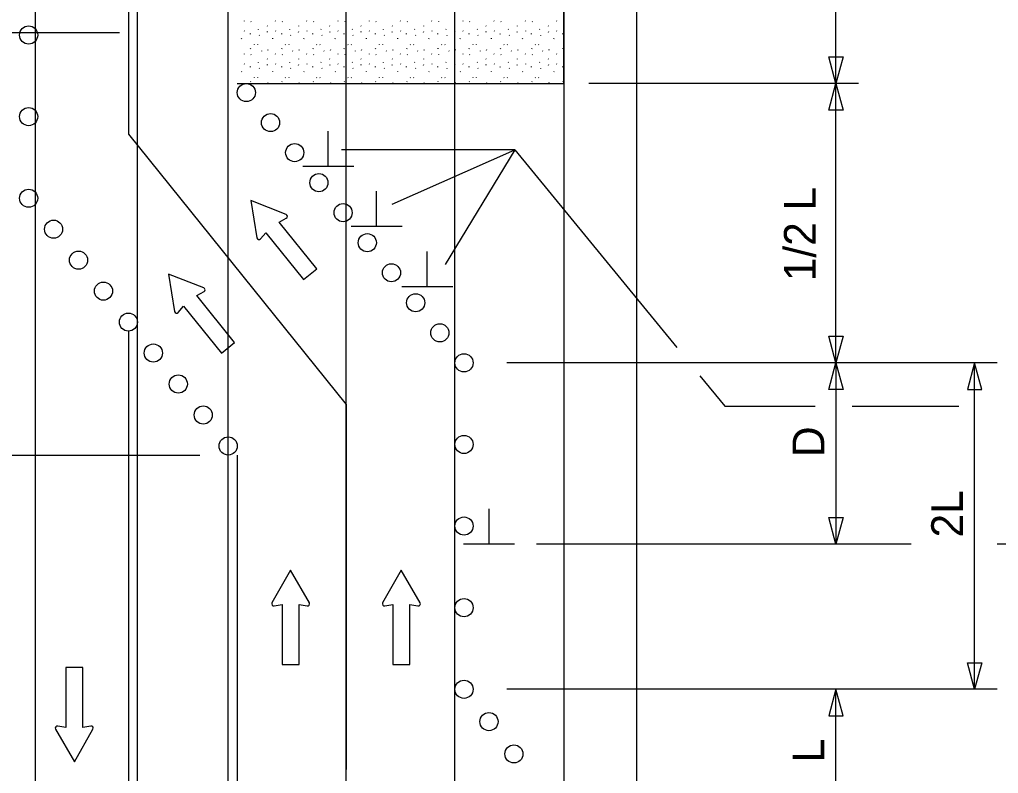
# Model space of a CAD drawing. Extents: x 16723 to 18475, y 7015 to 8267.
# Drawn here: x 17031.7 to 17247.5, y 7602.8 to 7769.1 of the extents above; entities that cross this region are included whole.
import ezdxf

# ---------------------------------------------------------------- set-up
doc = ezdxf.new("R2010")
doc.units = 0
for name, color, linetype in [('ALI_LEGAL_EX', 7, 'Continuous'), ('MT_SCRATCH_LEVEL_A', 7, 'Continuous'), ('MT_SCRATCH_LEVEL_E', 7, 'Continuous'), ('PAVT_EDGE_EX', 7, 'Continuous'), ('TRAFFIC_SIGNS_PR', 7, 'Continuous'), ('TYPICAL_TEXT_DIMEN_PR', 7, 'Continuous')]:
    doc.layers.add(name, color=color, linetype=linetype)

msp = doc.modelspace()

# ---------------------------------------------------------------- linework, layer by layer
at = {"layer": 'ALI_LEGAL_EX'}
for p, q in [((17057.71, 7347.02), (17057.71, 8219.23)), ((17077.71, 7347.02), (17077.71, 8219.23)), ((17103.71, 7341.97), (17103.71, 8214.17)), ((17127.71, 7341.97), (17127.71, 8214.17))]:
    msp.add_line(p, q, dxfattribs=at)
for points in [[(17077.71, 7754.97), (17077.71, 7766.97)], [(17103.71, 7741.97), (17103.71, 7766.97)], [(17127.71, 7741.97), (17127.71, 7766.97)], [(17057.71, 7641.97), (17057.71, 7666.97)], [(17077.71, 7641.97), (17077.71, 7666.97)], [(17103.71, 7641.97), (17103.71, 7666.97)], [(17127.71, 7641.97), (17127.71, 7666.97)]]:
    msp.add_lwpolyline(points, dxfattribs=at)
at = {"layer": 'MT_SCRATCH_LEVEL_A'}
for p, q in [((17151.71, 7867.21), (17151.71, 7754.97)), ((17151.71, 7754.97), (17151.71, 7783.03)), ((17081.21, 7768.78), (17081.26, 7768.7)), ((17082.74, 7768.64), (17082.79, 7768.56)), ((17088.1, 7768.78), (17088.15, 7768.7)), ((17089.63, 7768.64), (17089.68, 7768.56)), ((17094.98, 7768.78), (17095.04, 7768.7)), ((17096.51, 7768.64), (17096.57, 7768.56)), ((17101.87, 7768.78), (17101.92, 7768.7)), ((17103.4, 7768.64), (17103.45, 7768.56)), ((17108.76, 7768.78), (17108.81, 7768.7)), ((17110.29, 7768.64), (17110.34, 7768.56)), ((17115.65, 7768.78), (17115.7, 7768.7)), ((17117.18, 7768.64), (17117.23, 7768.56)), ((17122.53, 7768.78), (17122.59, 7768.7)), ((17124.06, 7768.64), (17124.12, 7768.56)), ((17129.42, 7768.78), (17129.47, 7768.7)), ((17130.95, 7768.64), (17131, 7768.56)), ((17136.31, 7768.78), (17136.36, 7768.7)), ((17137.84, 7768.64), (17137.89, 7768.56)), ((17143.2, 7768.78), (17143.25, 7768.7)), ((17144.73, 7768.64), (17144.78, 7768.56)), ((17150.08, 7768.78), (17150.14, 7768.7)), ((17151.61, 7768.64), (17151.67, 7768.56)), ((17081.26, 7766.57), (17081.31, 7766.49)), ((17082.54, 7766), (17082.55, 7765.88)), ((17084.38, 7766.85), (17084.43, 7766.97)), ((17084.57, 7765.65), (17084.62, 7765.58)), ((17086.31, 7767.72), (17086.36, 7767.65)), ((17086.35, 7766.32), (17086.4, 7766.44)), ((17088.15, 7766.57), (17088.2, 7766.49)), ((17089.43, 7766), (17089.44, 7765.88)), ((17091.27, 7766.85), (17091.32, 7766.97)), ((17091.46, 7765.65), (17091.51, 7765.58)), ((17093.19, 7767.72), (17093.24, 7767.65)), ((17093.24, 7766.32), (17093.29, 7766.44)), ((17095.03, 7766.57), (17095.08, 7766.49)), ((17096.31, 7766), (17096.33, 7765.88)), ((17098.16, 7766.85), (17098.21, 7766.97)), ((17098.34, 7765.65), (17098.4, 7765.58)), ((17100.08, 7767.72), (17100.13, 7767.65)), ((17100.12, 7766.32), (17100.17, 7766.44)), ((17101.92, 7766.57), (17101.97, 7766.49)), ((17103.2, 7766), (17103.22, 7765.88)), ((17105.04, 7766.85), (17105.1, 7766.97)), ((17105.23, 7765.65), (17105.28, 7765.58)), ((17106.97, 7767.72), (17107.02, 7767.65)), ((17107.01, 7766.32), (17107.06, 7766.44)), ((17108.81, 7766.57), (17108.86, 7766.49)), ((17110.09, 7766), (17110.1, 7765.88)), ((17111.93, 7766.85), (17111.98, 7766.97)), ((17112.12, 7765.65), (17112.17, 7765.58)), ((17113.86, 7767.72), (17113.91, 7767.65)), ((17113.9, 7766.32), (17113.95, 7766.44)), ((17115.69, 7766.57), (17115.75, 7766.49)), ((17116.98, 7766), (17116.99, 7765.88)), ((17118.82, 7766.85), (17118.87, 7766.97)), ((17119.01, 7765.65), (17119.06, 7765.58)), ((17120.74, 7767.72), (17120.8, 7767.65)), ((17120.79, 7766.32), (17120.84, 7766.44)), ((17122.58, 7766.57), (17122.63, 7766.49)), ((17123.86, 7766), (17123.88, 7765.88)), ((17125.71, 7766.85), (17125.76, 7766.97)), ((17125.89, 7765.65), (17125.95, 7765.58)), ((17127.63, 7767.72), (17127.68, 7767.65)), ((17127.67, 7766.32), (17127.73, 7766.44)), ((17129.47, 7766.57), (17129.52, 7766.49)), ((17130.75, 7766), (17130.76, 7765.88)), ((17132.59, 7766.85), (17132.65, 7766.97)), ((17132.78, 7765.65), (17132.83, 7765.58)), ((17134.52, 7767.72), (17134.57, 7767.65)), ((17134.56, 7766.32), (17134.61, 7766.44)), ((17136.36, 7766.57), (17136.41, 7766.49)), ((17137.64, 7766), (17137.65, 7765.88)), ((17139.48, 7766.85), (17139.53, 7766.97)), ((17139.67, 7765.65), (17139.72, 7765.58)), ((17141.41, 7767.72), (17141.46, 7767.65)), ((17141.45, 7766.32), (17141.5, 7766.44)), ((17143.24, 7766.57), (17143.3, 7766.49)), ((17144.53, 7766), (17144.54, 7765.88)), ((17146.37, 7766.85), (17146.42, 7766.97)), ((17146.56, 7765.65), (17146.61, 7765.58)), ((17148.29, 7767.72), (17148.35, 7767.65)), ((17148.34, 7766.32), (17148.39, 7766.44)), ((17150.13, 7766.57), (17150.19, 7766.49)), ((17151.42, 7766), (17151.43, 7765.88)), ((17080.64, 7764.82), (17080.69, 7764.94)), ((17083.42, 7763.58), (17083.47, 7763.51)), ((17084.16, 7763.55), (17084.21, 7763.48)), ((17087.53, 7764.82), (17087.58, 7764.94)), ((17090.31, 7763.58), (17090.36, 7763.51)), ((17091.05, 7763.55), (17091.1, 7763.48)), ((17094.41, 7764.82), (17094.47, 7764.94)), ((17097.2, 7763.58), (17097.25, 7763.51)), ((17097.94, 7763.55), (17097.99, 7763.48)), ((17101.3, 7764.82), (17101.35, 7764.94)), ((17104.09, 7763.58), (17104.14, 7763.51)), ((17104.82, 7763.55), (17104.88, 7763.48)), ((17108.19, 7764.82), (17108.24, 7764.94)), ((17110.97, 7763.58), (17111.03, 7763.51)), ((17111.71, 7763.55), (17111.76, 7763.48)), ((17115.08, 7764.82), (17115.13, 7764.94)), ((17117.86, 7763.58), (17117.91, 7763.51)), ((17118.6, 7763.55), (17118.65, 7763.48)), ((17121.96, 7764.82), (17122.02, 7764.94)), ((17124.75, 7763.58), (17124.8, 7763.51)), ((17125.49, 7763.55), (17125.54, 7763.48)), ((17128.85, 7764.82), (17128.9, 7764.94)), ((17131.64, 7763.58), (17131.69, 7763.51)), ((17132.37, 7763.55), (17132.42, 7763.48)), ((17135.74, 7764.82), (17135.79, 7764.94)), ((17138.52, 7763.58), (17138.58, 7763.51)), ((17139.26, 7763.55), (17139.31, 7763.48)), ((17142.63, 7764.82), (17142.68, 7764.94)), ((17145.41, 7763.58), (17145.46, 7763.51)), ((17146.15, 7763.55), (17146.2, 7763.48)), ((17149.51, 7764.82), (17149.57, 7764.94)), ((17081.21, 7761.5), (17081.26, 7761.42)), ((17082.66, 7762.62), (17082.71, 7762.74)), ((17082.74, 7761.36), (17082.79, 7761.28)), ((17085.03, 7762.18), (17085.08, 7762.1)), ((17086.48, 7762.33), (17086.53, 7762.44)), ((17088.1, 7761.5), (17088.15, 7761.42)), ((17089.55, 7762.62), (17089.6, 7762.74)), ((17089.63, 7761.36), (17089.68, 7761.28)), ((17091.92, 7762.18), (17091.97, 7762.1)), ((17093.37, 7762.33), (17093.42, 7762.44)), ((17094.98, 7761.5), (17095.04, 7761.42)), ((17096.43, 7762.62), (17096.49, 7762.74)), ((17096.51, 7761.36), (17096.57, 7761.28)), ((17098.8, 7762.18), (17098.86, 7762.1)), ((17100.25, 7762.33), (17100.31, 7762.44)), ((17101.87, 7761.5), (17101.92, 7761.42)), ((17103.32, 7762.62), (17103.37, 7762.74)), ((17103.4, 7761.36), (17103.45, 7761.28)), ((17105.69, 7762.18), (17105.74, 7762.1)), ((17107.14, 7762.33), (17107.19, 7762.44)), ((17108.76, 7761.5), (17108.81, 7761.42)), ((17110.21, 7762.62), (17110.26, 7762.74)), ((17110.29, 7761.36), (17110.34, 7761.28)), ((17112.58, 7762.18), (17112.63, 7762.1)), ((17114.03, 7762.33), (17114.08, 7762.44)), ((17115.65, 7761.5), (17115.7, 7761.42)), ((17117.1, 7762.62), (17117.15, 7762.74)), ((17117.18, 7761.36), (17117.23, 7761.28)), ((17119.47, 7762.18), (17119.52, 7762.1)), ((17120.92, 7762.33), (17120.97, 7762.44)), ((17122.53, 7761.5), (17122.59, 7761.42)), ((17123.98, 7762.62), (17124.04, 7762.74)), ((17124.06, 7761.36), (17124.12, 7761.28)), ((17126.35, 7762.18), (17126.41, 7762.1)), ((17127.8, 7762.33), (17127.85, 7762.44)), ((17129.42, 7761.5), (17129.47, 7761.42)), ((17130.87, 7762.62), (17130.92, 7762.74)), ((17130.95, 7761.36), (17131, 7761.28)), ((17133.24, 7762.18), (17133.29, 7762.1)), ((17134.69, 7762.33), (17134.74, 7762.44)), ((17136.31, 7761.5), (17136.36, 7761.42)), ((17137.76, 7762.62), (17137.81, 7762.74)), ((17137.84, 7761.36), (17137.89, 7761.28)), ((17140.13, 7762.18), (17140.18, 7762.1)), ((17141.58, 7762.33), (17141.63, 7762.44)), ((17143.2, 7761.5), (17143.25, 7761.42)), ((17144.65, 7762.62), (17144.7, 7762.74)), ((17144.73, 7761.36), (17144.78, 7761.28)), ((17147.02, 7762.18), (17147.07, 7762.1)), ((17148.47, 7762.33), (17148.52, 7762.44)), ((17150.08, 7761.5), (17150.14, 7761.42)), ((17151.53, 7762.62), (17151.59, 7762.74)), ((17151.61, 7761.36), (17151.67, 7761.28)), ((17081.26, 7759.29), (17081.31, 7759.21)), ((17084.38, 7759.57), (17084.43, 7759.69)), ((17086.31, 7760.44), (17086.36, 7760.36)), ((17088.15, 7759.29), (17088.2, 7759.21)), ((17091.27, 7759.57), (17091.32, 7759.69)), ((17093.19, 7760.44), (17093.24, 7760.36)), ((17095.03, 7759.29), (17095.08, 7759.21)), ((17098.16, 7759.57), (17098.21, 7759.69)), ((17100.08, 7760.44), (17100.13, 7760.36)), ((17101.92, 7759.29), (17101.97, 7759.21)), ((17105.04, 7759.57), (17105.1, 7759.69)), ((17106.97, 7760.44), (17107.02, 7760.36)), ((17108.81, 7759.29), (17108.86, 7759.21)), ((17111.93, 7759.57), (17111.98, 7759.69)), ((17113.86, 7760.44), (17113.91, 7760.36)), ((17115.69, 7759.29), (17115.75, 7759.21)), ((17118.82, 7759.57), (17118.87, 7759.69)), ((17120.74, 7760.44), (17120.8, 7760.36)), ((17122.58, 7759.29), (17122.63, 7759.21)), ((17125.71, 7759.57), (17125.76, 7759.69)), ((17127.63, 7760.44), (17127.68, 7760.36)), ((17129.47, 7759.29), (17129.52, 7759.21)), ((17132.59, 7759.57), (17132.65, 7759.69)), ((17134.52, 7760.44), (17134.57, 7760.36)), ((17136.36, 7759.29), (17136.41, 7759.21)), ((17139.48, 7759.57), (17139.53, 7759.69)), ((17141.41, 7760.44), (17141.46, 7760.36)), ((17143.24, 7759.29), (17143.3, 7759.21)), ((17146.37, 7759.57), (17146.42, 7759.69)), ((17148.29, 7760.44), (17148.35, 7760.36)), ((17150.13, 7759.29), (17150.19, 7759.21)), ((17080.64, 7757.53), (17080.69, 7757.65)), ((17082.54, 7758.71), (17082.55, 7758.6)), ((17084.57, 7758.37), (17084.62, 7758.29)), ((17086.35, 7759.04), (17086.4, 7759.15)), ((17087.53, 7757.53), (17087.58, 7757.65)), ((17089.43, 7758.71), (17089.44, 7758.6)), ((17091.46, 7758.37), (17091.51, 7758.29)), ((17093.24, 7759.04), (17093.29, 7759.15)), ((17094.41, 7757.53), (17094.47, 7757.65)), ((17096.31, 7758.71), (17096.33, 7758.6)), ((17098.34, 7758.37), (17098.4, 7758.29)), ((17100.12, 7759.04), (17100.17, 7759.15)), ((17101.3, 7757.53), (17101.35, 7757.65)), ((17103.2, 7758.71), (17103.22, 7758.6)), ((17105.23, 7758.37), (17105.28, 7758.29)), ((17107.01, 7759.04), (17107.06, 7759.15)), ((17108.19, 7757.53), (17108.24, 7757.65)), ((17110.09, 7758.71), (17110.1, 7758.6)), ((17112.12, 7758.37), (17112.17, 7758.29)), ((17113.9, 7759.04), (17113.95, 7759.15)), ((17115.08, 7757.53), (17115.13, 7757.65)), ((17116.98, 7758.71), (17116.99, 7758.6)), ((17119.01, 7758.37), (17119.06, 7758.29)), ((17120.79, 7759.04), (17120.84, 7759.15)), ((17121.96, 7757.53), (17122.02, 7757.65)), ((17123.86, 7758.71), (17123.88, 7758.6)), ((17125.89, 7758.37), (17125.95, 7758.29)), ((17127.67, 7759.04), (17127.73, 7759.15)), ((17128.85, 7757.53), (17128.9, 7757.65)), ((17130.75, 7758.71), (17130.76, 7758.6)), ((17132.78, 7758.37), (17132.83, 7758.29)), ((17134.56, 7759.04), (17134.61, 7759.15)), ((17135.74, 7757.53), (17135.79, 7757.65)), ((17137.64, 7758.71), (17137.65, 7758.6)), ((17139.67, 7758.37), (17139.72, 7758.29)), ((17141.45, 7759.04), (17141.5, 7759.15)), ((17142.63, 7757.53), (17142.68, 7757.65)), ((17144.53, 7758.71), (17144.54, 7758.6)), ((17146.56, 7758.37), (17146.61, 7758.29)), ((17148.34, 7759.04), (17148.39, 7759.15)), ((17149.51, 7757.53), (17149.57, 7757.65)), ((17151.42, 7758.71), (17151.43, 7758.6)), ((17079.71, 7754.97), (17151.71, 7754.97)), ((17079.71, 7754.97), (17151.71, 7754.97)), ((17082.66, 7755.34), (17082.71, 7755.45)), ((17083.42, 7756.3), (17083.47, 7756.22)), ((17084.16, 7756.27), (17084.21, 7756.19)), ((17086.48, 7755.04), (17086.53, 7755.16)), ((17089.55, 7755.34), (17089.6, 7755.45)), ((17090.31, 7756.3), (17090.36, 7756.22)), ((17091.05, 7756.27), (17091.1, 7756.19)), ((17093.37, 7755.04), (17093.42, 7755.16)), ((17096.43, 7755.34), (17096.49, 7755.45)), ((17097.2, 7756.3), (17097.25, 7756.22)), ((17097.94, 7756.27), (17097.99, 7756.19)), ((17100.25, 7755.04), (17100.31, 7755.16)), ((17103.32, 7755.34), (17103.37, 7755.45)), ((17104.09, 7756.3), (17104.14, 7756.22)), ((17104.82, 7756.27), (17104.88, 7756.19)), ((17107.14, 7755.04), (17107.19, 7755.16)), ((17110.21, 7755.34), (17110.26, 7755.45)), ((17110.97, 7756.3), (17111.03, 7756.22)), ((17111.71, 7756.27), (17111.76, 7756.19)), ((17114.03, 7755.04), (17114.08, 7755.16)), ((17117.1, 7755.34), (17117.15, 7755.45)), ((17117.86, 7756.3), (17117.91, 7756.22)), ((17118.6, 7756.27), (17118.65, 7756.19)), ((17120.92, 7755.04), (17120.97, 7755.16)), ((17123.98, 7755.34), (17124.04, 7755.45)), ((17124.75, 7756.3), (17124.8, 7756.22)), ((17125.49, 7756.27), (17125.54, 7756.19)), ((17127.8, 7755.04), (17127.85, 7755.16)), ((17130.87, 7755.34), (17130.92, 7755.45)), ((17131.64, 7756.3), (17131.69, 7756.22)), ((17132.37, 7756.27), (17132.42, 7756.19)), ((17134.69, 7755.04), (17134.74, 7755.16)), ((17137.76, 7755.34), (17137.81, 7755.45)), ((17138.52, 7756.3), (17138.58, 7756.22)), ((17139.26, 7756.27), (17139.31, 7756.19)), ((17141.58, 7755.04), (17141.63, 7755.16)), ((17144.65, 7755.34), (17144.7, 7755.45)), ((17145.41, 7756.3), (17145.46, 7756.22)), ((17146.15, 7756.27), (17146.2, 7756.19)), ((17148.47, 7755.04), (17148.52, 7755.16)), ((17151.53, 7755.34), (17151.59, 7755.45))]:
    msp.add_line(p, q, dxfattribs=at)
at = {"layer": 'MT_SCRATCH_LEVEL_E'}
for p, q in [((17082.7, 7729.14), (17084.04, 7720.92)), ((17090.47, 7726.1), (17082.7, 7729.14)), ((17082.7, 7729.14), (17084.04, 7720.92)), ((17090.47, 7726.1), (17082.7, 7729.14)), ((17088.94, 7724.4), (17090.52, 7725.27)), ((17088.94, 7724.4), (17090.52, 7725.27)), ((17097.26, 7714.07), (17088.94, 7724.4)), ((17097.26, 7714.07), (17088.94, 7724.4)), ((17084.84, 7720.69), (17086.03, 7722.05)), ((17084.84, 7720.69), (17086.03, 7722.05)), ((17086.03, 7722.05), (17094.34, 7711.73)), ((17086.03, 7722.05), (17094.34, 7711.73)), ((17094.34, 7711.73), (17097.26, 7714.07)), ((17094.34, 7711.73), (17097.26, 7714.07)), ((17064.56, 7712.93), (17065.9, 7704.71)), ((17072.33, 7709.89), (17064.56, 7712.93)), ((17064.56, 7712.93), (17065.9, 7704.71)), ((17072.33, 7709.89), (17064.56, 7712.93)), ((17070.8, 7708.19), (17072.38, 7709.06)), ((17070.8, 7708.19), (17072.38, 7709.06)), ((17079.12, 7697.86), (17070.8, 7708.19)), ((17079.12, 7697.86), (17070.8, 7708.19)), ((17066.7, 7704.48), (17067.89, 7705.84)), ((17066.7, 7704.48), (17067.89, 7705.84)), ((17067.89, 7705.84), (17076.2, 7695.52)), ((17067.89, 7705.84), (17076.2, 7695.52)), ((17076.2, 7695.52), (17079.12, 7697.86)), ((17076.2, 7695.52), (17079.12, 7697.86)), ((17091.48, 7647.66), (17087.37, 7640.42)), ((17091.48, 7647.66), (17087.37, 7640.42)), ((17095.62, 7640.42), (17091.48, 7647.66)), ((17095.62, 7640.42), (17091.48, 7647.66)), ((17115.88, 7647.66), (17111.77, 7640.42)), ((17115.88, 7647.66), (17111.77, 7640.42)), ((17120.03, 7640.42), (17115.88, 7647.66)), ((17120.03, 7640.42), (17115.88, 7647.66)), ((17087.85, 7639.74), (17089.63, 7640.05)), ((17087.85, 7639.74), (17089.63, 7640.05)), ((17089.63, 7640.05), (17089.63, 7626.79)), ((17089.63, 7640.05), (17089.63, 7626.79)), ((17093.37, 7626.79), (17093.37, 7640.05)), ((17093.37, 7640.05), (17095.15, 7639.74)), ((17093.37, 7626.79), (17093.37, 7640.05)), ((17093.37, 7640.05), (17095.15, 7639.74)), ((17112.25, 7639.74), (17114.03, 7640.05)), ((17112.25, 7639.74), (17114.03, 7640.05)), ((17114.03, 7640.05), (17114.03, 7626.79)), ((17114.03, 7640.05), (17114.03, 7626.79)), ((17117.77, 7626.79), (17117.77, 7640.05)), ((17117.77, 7640.05), (17119.55, 7639.74)), ((17117.77, 7626.79), (17117.77, 7640.05)), ((17117.77, 7640.05), (17119.55, 7639.74)), ((17045.64, 7626.2), (17041.9, 7626.2)), ((17041.9, 7626.2), (17041.9, 7612.95)), ((17045.64, 7626.2), (17041.9, 7626.2)), ((17041.9, 7626.2), (17041.9, 7612.95)), ((17045.64, 7612.95), (17045.64, 7626.2)), ((17045.64, 7612.95), (17045.64, 7626.2)), ((17089.63, 7626.79), (17093.37, 7626.79)), ((17089.63, 7626.79), (17093.37, 7626.79)), ((17114.03, 7626.79), (17117.77, 7626.79)), ((17114.03, 7626.79), (17117.77, 7626.79)), ((17039.64, 7612.58), (17043.79, 7605.34)), ((17039.64, 7612.58), (17043.79, 7605.34)), ((17041.9, 7612.95), (17040.12, 7613.26)), ((17041.9, 7612.95), (17040.12, 7613.26)), ((17043.79, 7605.34), (17047.9, 7612.58)), ((17043.79, 7605.34), (17047.9, 7612.58)), ((17047.42, 7613.26), (17045.64, 7612.95)), ((17047.42, 7613.26), (17045.64, 7612.95))]:
    msp.add_line(p, q, dxfattribs=at)
for centre, start, end in [((17090.29, 7725.67), 298.877, 68.6139), ((17090.29, 7725.67), 298.877, 68.6139), ((17084.49, 7721), 189.2656, 318.8046), ((17084.49, 7721), 189.2656, 318.8046), ((17072.15, 7709.46), 298.877, 68.6139), ((17072.15, 7709.46), 298.877, 68.6139), ((17066.35, 7704.79), 189.2656, 318.8046), ((17066.35, 7704.79), 189.2656, 318.8046), ((17087.77, 7640.2), 150.4248, 279.9638), ((17087.77, 7640.2), 150.4248, 279.9638), ((17095.21, 7640.2), 260.0362, 29.7731), ((17095.21, 7640.2), 260.0362, 29.7731), ((17112.17, 7640.2), 150.4248, 279.9638), ((17112.17, 7640.2), 150.4248, 279.9638), ((17119.62, 7640.2), 260.0362, 29.7731), ((17119.62, 7640.2), 260.0362, 29.7731), ((17040.05, 7612.8), 80.0362, 209.7731), ((17040.05, 7612.8), 80.0362, 209.7731), ((17047.49, 7612.8), 330.4248, 99.9638), ((17047.49, 7612.8), 330.4248, 99.9638)]:
    msp.add_arc(centre, 0.463, start, end, dxfattribs=at)
at = {"layer": 'PAVT_EDGE_EX'}
for p, q in [((17035.15, 8267.39), (17035.15, 7438.21)), ((17151.71, 8214.17), (17151.71, 7352.81)), ((17167.71, 8214.17), (17167.71, 7352.81)), ((17055.71, 7913.53), (17055.71, 7743.81)), ((17055.71, 7743.81), (17103.71, 7684.19)), ((17055.71, 7700.35), (17055.71, 7352.81)), ((17103.71, 7684.19), (17103.71, 7603.63)), ((17079.71, 7673.03), (17079.71, 7352.81))]:
    msp.add_line(p, q, dxfattribs=at)
at = {"layer": 'TRAFFIC_SIGNS_PR'}
for centre in [(17033.71, 7765.67), (17081.71, 7752.97), (17033.71, 7747.67), (17087.05, 7746.35), (17092.38, 7739.73), (17097.71, 7733.1), (17033.71, 7729.67), (17033.71, 7729.67), (17033.71, 7729.67), (17033.71, 7729.67), (17103.05, 7726.48), (17039.21, 7722.84), (17108.38, 7719.86), (17044.71, 7716.01), (17113.71, 7713.23), (17050.21, 7709.18), (17119.05, 7706.61), (17055.71, 7702.35), (17124.38, 7699.98), (17061.21, 7695.52), (17129.71, 7693.36), (17066.71, 7688.69), (17072.21, 7681.86), (17129.71, 7675.36), (17077.71, 7675.03), (17129.71, 7657.36), (17129.71, 7639.36), (17129.71, 7621.36), (17135.21, 7614.23), (17140.71, 7607.1)]:
    msp.add_circle(centre, 2, dxfattribs=at)
at = {"layer": 'TYPICAL_TEXT_DIMEN_PR'}
for p, q in [((17211.71, 7754.97), (17211.71, 7783.03)), ((17028.75, 7766.24), (17053.75, 7766.24)), ((17211.71, 7754.97), (17210.14, 7760.84)), ((17210.14, 7760.84), (17211.71, 7760.84)), ((17211.71, 7760.84), (17213.28, 7760.84)), ((17213.28, 7760.84), (17211.71, 7754.97)), ((17216.71, 7754.97), (17157.22, 7754.97)), ((17210.14, 7749.11), (17211.71, 7754.97)), ((17211.71, 7754.97), (17213.28, 7749.11)), ((17211.71, 7693.36), (17211.71, 7754.97)), ((17211.71, 7749.11), (17210.14, 7749.11)), ((17213.28, 7749.11), (17211.71, 7749.11)), ((17099.76, 7736.67), (17099.76, 7744.45)), ((17140.94, 7740.33), (17102.73, 7740.33)), ((17113.89, 7728.33), (17140.94, 7740.33)), ((17140.94, 7740.33), (17125.54, 7715.06)), ((17140.94, 7740.33), (17176.61, 7696.77)), ((17105.39, 7736.67), (17094.14, 7736.67)), ((17110.42, 7723.45), (17110.42, 7731.24)), ((17116.05, 7723.45), (17104.8, 7723.45)), ((17121.59, 7710.13), (17121.59, 7717.92)), ((17127.22, 7710.13), (17115.97, 7710.13)), ((17211.71, 7693.36), (17210.14, 7699.22)), ((17210.14, 7699.22), (17211.71, 7699.22)), ((17211.71, 7699.22), (17213.28, 7699.22)), ((17213.28, 7699.22), (17211.71, 7693.36)), ((17247.29, 7693.36), (17139.17, 7693.36)), ((17210.14, 7687.5), (17211.71, 7693.36)), ((17211.71, 7693.36), (17211.71, 7653.36)), ((17211.71, 7693.36), (17213.28, 7687.5)), ((17242.29, 7693.36), (17240.72, 7687.5)), ((17243.86, 7687.5), (17242.29, 7693.36)), ((17242.29, 7621.36), (17242.29, 7693.36)), ((17181.73, 7690.52), (17187.21, 7683.83)), ((17211.71, 7687.5), (17210.14, 7687.5)), ((17213.28, 7687.5), (17211.71, 7687.5)), ((17240.72, 7687.5), (17242.29, 7687.5)), ((17242.29, 7687.5), (17243.86, 7687.5)), ((17187.21, 7683.83), (17207.14, 7683.83)), ((17215.27, 7683.83), (17238.85, 7683.83)), ((16923.21, 7673.03), (17071.46, 7673.03)), ((17135.22, 7653.36), (17135.22, 7661.15)), ((17211.71, 7653.36), (17210.14, 7659.22)), ((17210.14, 7659.22), (17211.71, 7659.22)), ((17211.71, 7659.22), (17213.28, 7659.22)), ((17213.28, 7659.22), (17211.71, 7653.36)), ((17140.85, 7653.36), (17129.6, 7653.36)), ((17228.28, 7653.36), (17145.69, 7653.36)), ((17216.71, 7653.36), (17190.71, 7653.36)), ((17267.51, 7653.36), (17247.29, 7653.36)), ((17242.29, 7621.36), (17240.72, 7627.22)), ((17240.72, 7627.22), (17242.29, 7627.22)), ((17242.29, 7627.22), (17243.86, 7627.22)), ((17243.86, 7627.22), (17242.29, 7621.36)), ((17247.29, 7621.36), (17139.17, 7621.36)), ((17211.71, 7621.36), (17210.14, 7615.5)), ((17211.71, 7590.85), (17211.71, 7621.36)), ((17213.28, 7615.5), (17211.71, 7621.36)), ((17210.14, 7615.5), (17211.71, 7615.5)), ((17211.71, 7615.5), (17213.28, 7615.5))]:
    msp.add_line(p, q, dxfattribs=at)

# ---------------------------------------------------------------- texts
for s, p in [('1/2 L', (17207.26, 7711.36)), ('D', (17209.15, 7672.58)), ('2L', (17239.73, 7654.85)), ('L', (17209.15, 7605.25))]:
    msp.add_text(s, height=7, rotation=90, dxfattribs=at).set_placement(p)

doc.saveas('drawing.dxf')
